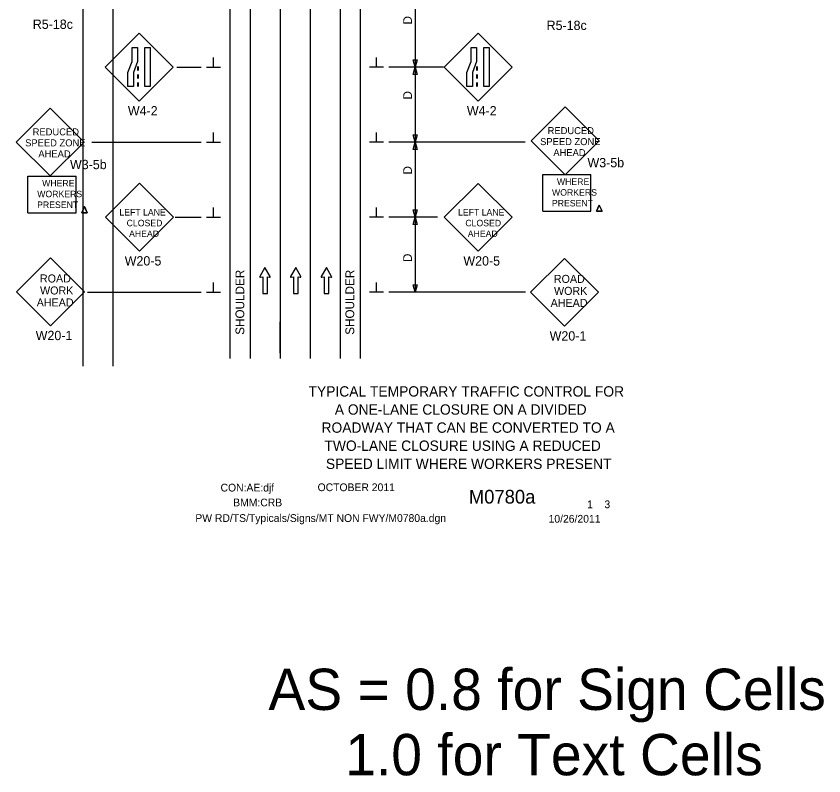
# Model space of a CAD drawing. Extents: x 16758 to 19504, y 5731 to 6944.
# Drawn here: x 16927 to 17573, y 5731 to 6338 of the extents above; entities that cross this region are included whole.
import ezdxf

# ---------------------------------------------------------------- set-up
doc = ezdxf.new("R2010")
doc.units = 0
for name, color, linetype in [('ALI_LEGAL_EX', 7, 'Continuous'), ('BORDER', 7, 'Continuous'), ('BORDER_SIGNAL_WO', 7, 'Continuous'), ('MT_SCRATCH_LEVEL_E', 7, 'Continuous'), ('PAVT_EDGE_EX', 7, 'Continuous'), ('TRAFFIC_SIGNS_PR', 7, 'Continuous'), ('TYPICAL_TEXT_DIMEN_PR', 7, 'Continuous')]:
    doc.layers.add(name, color=color, linetype=linetype)

msp = doc.modelspace()

# ---------------------------------------------------------------- linework, layer by layer
at = {"layer": 'ALI_LEGAL_EX'}
for p, q in [((16980.68, 6944.08), (16980.68, 6125.94)), ((17004.68, 6944.08), (17004.68, 6125.94)), ((16980.68, 6922.21), (16980.68, 6058.3)), ((17004.68, 6922.21), (17004.68, 6058.3)), ((17138.25, 6893.66), (17138.25, 6064.47)), ((17162.25, 6893.66), (17162.25, 6064.47))]:
    msp.add_line(p, q, dxfattribs=at)
for points in [[(17138.25, 6293.66), (17138.25, 6268.66)], [(17162.25, 6293.66), (17162.25, 6268.66)], [(17138.25, 6193.66), (17138.25, 6168.66)], [(17162.25, 6193.66), (17162.25, 6168.66)], [(17138.25, 6068.66), (17138.25, 6093.66)], [(17138.25, 6068.66), (17138.25, 6093.66)], [(17162.25, 6093.66), (17162.25, 6068.66)]]:
    msp.add_lwpolyline(points, dxfattribs=at)
at = {"layer": 'MT_SCRATCH_LEVEL_E'}
for p, q in [((17126.22, 6137.3), (17122.11, 6130.06)), ((17126.22, 6137.3), (17122.11, 6130.06)), ((17130.37, 6130.06), (17126.22, 6137.3)), ((17130.37, 6130.06), (17126.22, 6137.3)), ((17150.78, 6137.3), (17146.67, 6130.06)), ((17150.78, 6137.3), (17146.67, 6130.06)), ((17154.92, 6130.06), (17150.78, 6137.3)), ((17154.92, 6130.06), (17150.78, 6137.3)), ((17175.34, 6137.3), (17171.22, 6130.06)), ((17175.34, 6137.3), (17171.22, 6130.06)), ((17179.48, 6130.06), (17175.34, 6137.3)), ((17179.48, 6130.06), (17175.34, 6137.3)), ((17122.59, 6129.37), (17124.37, 6129.69)), ((17122.59, 6129.37), (17124.37, 6129.69)), ((17124.37, 6129.69), (17124.37, 6116.43)), ((17124.37, 6129.69), (17124.37, 6116.43)), ((17128.11, 6116.43), (17128.11, 6129.69)), ((17128.11, 6129.69), (17129.89, 6129.37)), ((17128.11, 6116.43), (17128.11, 6129.69)), ((17128.11, 6129.69), (17129.89, 6129.37)), ((17147.15, 6129.37), (17148.92, 6129.69)), ((17147.15, 6129.37), (17148.92, 6129.69)), ((17148.92, 6129.69), (17148.92, 6116.43)), ((17148.92, 6129.69), (17148.92, 6116.43)), ((17152.67, 6116.43), (17152.67, 6129.69)), ((17152.67, 6129.69), (17154.44, 6129.37)), ((17152.67, 6116.43), (17152.67, 6129.69)), ((17152.67, 6129.69), (17154.44, 6129.37)), ((17171.71, 6129.37), (17173.48, 6129.69)), ((17171.71, 6129.37), (17173.48, 6129.69)), ((17173.48, 6129.69), (17173.48, 6116.43)), ((17173.48, 6129.69), (17173.48, 6116.43)), ((17177.23, 6116.43), (17177.23, 6129.69)), ((17177.23, 6129.69), (17179, 6129.37)), ((17177.23, 6116.43), (17177.23, 6129.69)), ((17177.23, 6129.69), (17179, 6129.37)), ((17124.37, 6116.43), (17128.11, 6116.43)), ((17124.37, 6116.43), (17128.11, 6116.43)), ((17148.92, 6116.43), (17152.67, 6116.43)), ((17148.92, 6116.43), (17152.67, 6116.43)), ((17173.48, 6116.43), (17177.23, 6116.43)), ((17173.48, 6116.43), (17177.23, 6116.43))]:
    msp.add_line(p, q, dxfattribs=at)
for centre, start, end in [((17122.51, 6129.83), 150.42484, 279.96381), ((17122.51, 6129.83), 150.42484, 279.96381), ((17129.96, 6129.83), 260.03619, 29.77312), ((17129.96, 6129.83), 260.03619, 29.77312), ((17147.07, 6129.83), 150.42484, 279.96381), ((17147.07, 6129.83), 150.42484, 279.96381), ((17154.51, 6129.83), 260.03619, 29.77312), ((17154.51, 6129.83), 260.03619, 29.77312), ((17171.63, 6129.83), 150.42484, 279.96381), ((17171.63, 6129.83), 150.42484, 279.96381), ((17179.07, 6129.83), 260.03619, 29.77312), ((17179.07, 6129.83), 260.03619, 29.77312)]:
    msp.add_arc(centre, 0.463, start, end, dxfattribs=at)
at = {"layer": 'PAVT_EDGE_EX'}
for p, q in [((17098.25, 6924.45), (17098.25, 6064.47)), ((17114.25, 6924.45), (17114.25, 6064.47)), ((17186.25, 6924.45), (17186.25, 6064.47)), ((17202.25, 6924.45), (17202.25, 6064.47))]:
    msp.add_line(p, q, dxfattribs=at)
at = {"layer": 'TRAFFIC_SIGNS_PR'}
for p, q in [((17025.66, 6324.62), (16998.51, 6297.47)), ((17052.81, 6297.47), (17025.66, 6324.62)), ((17296.66, 6324.65), (17269.51, 6297.49)), ((17323.82, 6297.49), (17296.66, 6324.65)), ((16998.51, 6297.47), (17025.66, 6270.31)), ((17024.41, 6297.96), (17024.41, 6294.76)), ((17024.81, 6297.96), (17024.81, 6294.76)), ((17025.66, 6270.31), (17052.81, 6297.47)), ((17269.51, 6297.49), (17296.66, 6270.34)), ((17295.42, 6297.98), (17295.42, 6294.78)), ((17295.82, 6297.98), (17295.82, 6294.78)), ((17296.66, 6270.34), (17323.82, 6297.49)), ((17024.41, 6291.56), (17024.41, 6288.36)), ((17024.81, 6291.56), (17024.81, 6288.36)), ((17295.42, 6291.58), (17295.42, 6288.38)), ((17295.82, 6291.58), (17295.82, 6288.38)), ((17024.41, 6285.16), (17024.41, 6281.96)), ((17024.81, 6285.16), (17024.81, 6281.96)), ((17295.42, 6285.18), (17295.42, 6281.98)), ((17295.82, 6285.18), (17295.82, 6281.98)), ((16954.46, 6264.77), (16927.3, 6237.61)), ((16981.61, 6237.61), (16954.46, 6264.77)), ((17366.13, 6265.76), (17338.97, 6238.61)), ((17393.28, 6238.61), (17366.13, 6265.76)), ((16927.3, 6237.61), (16954.46, 6210.46)), ((16954.46, 6210.46), (16981.61, 6237.61)), ((17338.97, 6238.61), (17366.13, 6211.46)), ((17366.13, 6211.46), (17393.28, 6238.61)), ((17348.28, 6211.6), (17386.68, 6211.6)), ((17348.28, 6182.28), (17348.28, 6211.6)), ((17386.68, 6182.28), (17386.68, 6211.6)), ((16936.77, 6210.35), (16975.17, 6210.35)), ((16936.77, 6181.03), (16936.77, 6210.35)), ((16975.17, 6181.03), (16975.17, 6210.35)), ((17025.92, 6204.57), (16998.76, 6177.42)), ((17053.07, 6177.42), (17025.92, 6204.57)), ((17296.66, 6204.55), (17269.51, 6177.4)), ((17323.82, 6177.4), (17296.66, 6204.55)), ((16936.77, 6181.03), (16975.17, 6181.03)), ((17348.28, 6182.28), (17386.68, 6182.28)), ((16998.76, 6177.42), (17025.92, 6150.26)), ((17025.92, 6150.26), (17053.07, 6177.42)), ((17269.51, 6177.4), (17296.66, 6150.24)), ((17296.66, 6150.24), (17323.82, 6177.4)), ((16954.77, 6144.88), (16927.62, 6117.72)), ((16981.93, 6117.72), (16954.77, 6144.88)), ((17365.62, 6144.55), (17338.47, 6117.39)), ((17392.77, 6117.39), (17365.62, 6144.55)), ((16927.62, 6117.72), (16954.77, 6090.57)), ((16954.77, 6090.57), (16981.93, 6117.72)), ((17338.47, 6117.39), (17365.62, 6090.24)), ((17365.62, 6090.24), (17392.77, 6117.39))]:
    msp.add_line(p, q, dxfattribs=at)
for points in [[(17024.41, 6313.2), (17024.41, 6302.02), (17021.07, 6293.14), (17021.07, 6281.96), (17016.58, 6281.96), (17016.58, 6293.14), (17019.92, 6302.02), (17019.92, 6313.2)], [(17034.55, 6313.2), (17034.55, 6281.96), (17030.06, 6281.96), (17030.06, 6313.2)], [(17295.42, 6313.23), (17295.42, 6302.05), (17292.07, 6293.17), (17292.07, 6281.98), (17287.58, 6281.98), (17287.58, 6293.17), (17290.92, 6302.05), (17290.92, 6313.23)], [(17305.55, 6313.23), (17305.55, 6281.98), (17301.06, 6281.98), (17301.06, 6313.23)]]:
    msp.add_lwpolyline(points, close=True, dxfattribs=at)
for points in [[(16981.91, 6185.97), (16979.68, 6181.03)], [(16979.68, 6181.03), (16981.91, 6185.97)], [(16984.15, 6181.03), (16981.91, 6185.97)], [(16981.91, 6185.97), (16984.15, 6181.03)], [(17393.43, 6187.22), (17391.19, 6182.28)], [(17391.19, 6182.28), (17393.43, 6187.22)], [(17395.66, 6182.28), (17393.43, 6187.22)], [(17393.43, 6187.22), (17395.66, 6182.28)], [(16979.68, 6181.03), (16984.15, 6181.03)], [(16984.15, 6181.03), (16979.68, 6181.03)], [(17391.19, 6182.28), (17395.66, 6182.28)], [(17395.66, 6182.28), (17391.19, 6182.28)]]:
    msp.add_lwpolyline(points, dxfattribs=at)
at = {"layer": 'TYPICAL_TEXT_DIMEN_PR'}
for p, q in [((17246.25, 6357.4), (17246.25, 6297.4)), ((17085.12, 6297.4), (17085.12, 6305.18)), ((17215.38, 6297.4), (17215.38, 6305.18)), ((17246.25, 6297.4), (17244.68, 6303.26)), ((17244.68, 6303.26), (17246.25, 6303.26)), ((17246.25, 6297.4), (17244.68, 6303.26)), ((17244.68, 6303.26), (17246.25, 6303.26)), ((17246.25, 6303.26), (17247.82, 6303.26)), ((17247.82, 6303.26), (17246.25, 6297.4)), ((17246.25, 6303.26), (17247.82, 6303.26)), ((17247.82, 6303.26), (17246.25, 6297.4)), ((17055.82, 6297.4), (17075.25, 6297.4)), ((17079.5, 6297.4), (17090.75, 6297.4)), ((17221, 6297.4), (17209.75, 6297.4)), ((17269, 6297.4), (17225.25, 6297.4)), ((17244.68, 6291.53), (17246.25, 6297.4)), ((17246.25, 6297.4), (17246.25, 6237.4)), ((17246.25, 6297.4), (17247.82, 6291.53)), ((17246.25, 6291.53), (17244.68, 6291.53)), ((17247.82, 6291.53), (17246.25, 6291.53)), ((17085.12, 6237.4), (17085.12, 6245.18)), ((17215.38, 6237.4), (17215.38, 6245.18)), ((16987.89, 6237.4), (17075.25, 6237.4)), ((17079.5, 6237.4), (17090.75, 6237.4)), ((17221, 6237.4), (17209.75, 6237.4)), ((17334.24, 6237.4), (17225.25, 6237.4)), ((17246.25, 6237.4), (17244.68, 6243.26)), ((17244.68, 6243.26), (17246.25, 6243.26)), ((17244.68, 6231.53), (17246.25, 6237.4)), ((17244.68, 6231.53), (17246.25, 6237.4)), ((17246.25, 6243.26), (17247.82, 6243.26)), ((17247.82, 6243.26), (17246.25, 6237.4)), ((17246.25, 6237.4), (17246.25, 6177.4)), ((17246.25, 6237.4), (17247.82, 6231.53)), ((17246.25, 6237.4), (17247.82, 6231.53)), ((17246.25, 6231.53), (17244.68, 6231.53)), ((17246.25, 6231.53), (17244.68, 6231.53)), ((17247.82, 6231.53), (17246.25, 6231.53)), ((17247.82, 6231.53), (17246.25, 6231.53)), ((17085.12, 6177.4), (17085.12, 6185.18)), ((17215.38, 6177.4), (17215.38, 6185.18)), ((17246.25, 6177.4), (17244.68, 6183.26)), ((17244.68, 6183.26), (17246.25, 6183.26)), ((17246.25, 6177.4), (17244.68, 6183.26)), ((17244.68, 6183.26), (17246.25, 6183.26)), ((17246.25, 6183.26), (17247.82, 6183.26)), ((17247.82, 6183.26), (17246.25, 6177.4)), ((17246.25, 6183.26), (17247.82, 6183.26)), ((17247.82, 6183.26), (17246.25, 6177.4)), ((17054.52, 6177.4), (17075.25, 6177.4)), ((17079.5, 6177.4), (17090.75, 6177.4)), ((17221, 6177.4), (17209.75, 6177.4)), ((17264.25, 6177.4), (17225.25, 6177.4)), ((17244.68, 6171.53), (17246.25, 6177.4)), ((17246.25, 6177.4), (17246.25, 6117.4)), ((17246.25, 6177.4), (17247.82, 6171.53)), ((17246.25, 6171.53), (17244.68, 6171.53)), ((17247.82, 6171.53), (17246.25, 6171.53)), ((17085.12, 6117.4), (17085.12, 6125.18)), ((17215.38, 6117.4), (17215.38, 6125.18)), ((17246.25, 6117.4), (17244.68, 6123.26)), ((17244.68, 6123.26), (17246.25, 6123.26)), ((17246.25, 6123.26), (17247.82, 6123.26)), ((17247.82, 6123.26), (17246.25, 6117.4)), ((16984.46, 6117.4), (17075.25, 6117.4)), ((17079.5, 6117.4), (17090.75, 6117.4)), ((17221, 6117.4), (17209.75, 6117.4)), ((17334.39, 6117.4), (17225.25, 6117.4))]:
    msp.add_line(p, q, dxfattribs=at)

# ---------------------------------------------------------------- texts
at = {"layer": 'BORDER'}
for s, p in [('TYPICAL TEMPORARY TRAFFIC CONTROL FOR', (17161.04, 6033.99)), ('A ONE-LANE CLOSURE ON A DIVIDED', (17182.02, 6019.51)), ('ROADWAY THAT CAN BE CONVERTED TO A', (17171.42, 6005.04)), ('TWO-LANE CLOSURE USING A REDUCED ', (17173.75, 5990.56)), ('SPEED LIMIT WHERE WORKERS PRESENT', (17174.92, 5976.08))]:
    msp.add_text(s, height=8.2598, dxfattribs=at).set_placement(p)
at = {"layer": 'BORDER_SIGNAL_WO'}
for s, height, p in [('CON:AE:djf', 6.2, (17090.69, 5958.06)), ('    OCTOBER 2011    ', 6.2, (17159.08, 5958.34)), ('    M0780a   ', 11, (17272.86, 5948.38)), ('BMM:CRB   ', 6.2, (17100.81, 5946.17)), (' 1    3 ', 6.2, (17381.45, 5944.7)), ('PW RD/TS/Typicals/Signs/MT NON FWY/M0780a.dgn    ', 6.2, (17070.55, 5933.71)), ('10/26/2011    ', 6.2, (17352.93, 5933.13)), ('AS = 0.8 for Sign Cells', 33.0301, (17128.99, 5783.31)), ('     1.0 for Text Cells', 33.0301, (17128.99, 5731.08))]:
    msp.add_text(s, height=height, dxfattribs=at).set_placement(p)
at = {"layer": 'TRAFFIC_SIGNS_PR'}
for s, height, p in [('R5-18c', 7.44, (16940.61, 6328.09)), ('R5-18c', 7.44, (17351.36, 6327.21)), ('W4-2', 7.44, (17016.62, 6258.87)), ('W4-2', 7.44, (17287.62, 6258.9)), ('REDUCED', 5.6, (16940.51, 6242.92)), ('REDUCED', 5.6, (17352.18, 6243.92)), ('SPEED ZONE', 5.6, (16934.5, 6234.12)), ('SPEED ZONE', 5.6, (17346.18, 6235.12)), ('AHEAD', 5.6, (16945.07, 6225.32)), ('AHEAD', 5.6, (17356.74, 6226.32)), ('W3-5b', 7.44, (17384.03, 6217.39)), ('W3-5b', 7.44, (16970.35, 6215.9)), ('WHERE', 5.2, (16948.08, 6202.03)), ('WHERE', 5.2, (17359.59, 6203.28)), ('WORKERS', 5.2, (16944.15, 6193.43)), ('WORKERS', 5.2, (17355.66, 6194.68)), ('PRESENT', 5.2, (16944.08, 6184.83)), ('PRESENT', 5.2, (17355.59, 6186.08)), ('LEFT LANE', 5.2, (17009.8, 6178.81)), ('LEFT LANE', 5.2, (17280.54, 6178.79)), ('CLOSED', 5.2, (17015.63, 6170.21)), ('CLOSED', 5.2, (17286.38, 6170.19)), ('AHEAD', 5.2, (17017.57, 6161.61)), ('AHEAD', 5.2, (17288.32, 6161.59)), ('W20-5', 7.44, (17014.09, 6138.82)), ('W20-5', 7.44, (17284.84, 6138.8)), ('ROAD', 6.4, (16946.32, 6125.26)), ('ROAD', 6.4, (17357.16, 6124.93)), ('WORK', 6.4, (16946.42, 6115.66)), ('WORK', 6.4, (17357.27, 6115.33)), ('AHEAD', 6.4, (16943.73, 6106.06)), ('AHEAD', 6.4, (17354.58, 6105.73)), ('W20-1', 7.44, (16942.94, 6079.13)), ('W20-1', 7.44, (17353.79, 6078.8))]:
    msp.add_text(s, height=height, dxfattribs=at).set_placement(p)
at = {"layer": 'TYPICAL_TEXT_DIMEN_PR'}
for s, p in [('D', (17243.69, 6331.61)), ('D', (17243.69, 6271.61)), ('D', (17243.69, 6211.61)), ('D', (17243.69, 6141.61)), ('SHOULDER', (17109.67, 6083.41)), ('SHOULDER', (17197.53, 6083.41))]:
    msp.add_text(s, height=7, rotation=90, dxfattribs=at).set_placement(p)

doc.saveas('drawing.dxf')
